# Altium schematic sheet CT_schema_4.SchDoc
size 367 x 243 mm
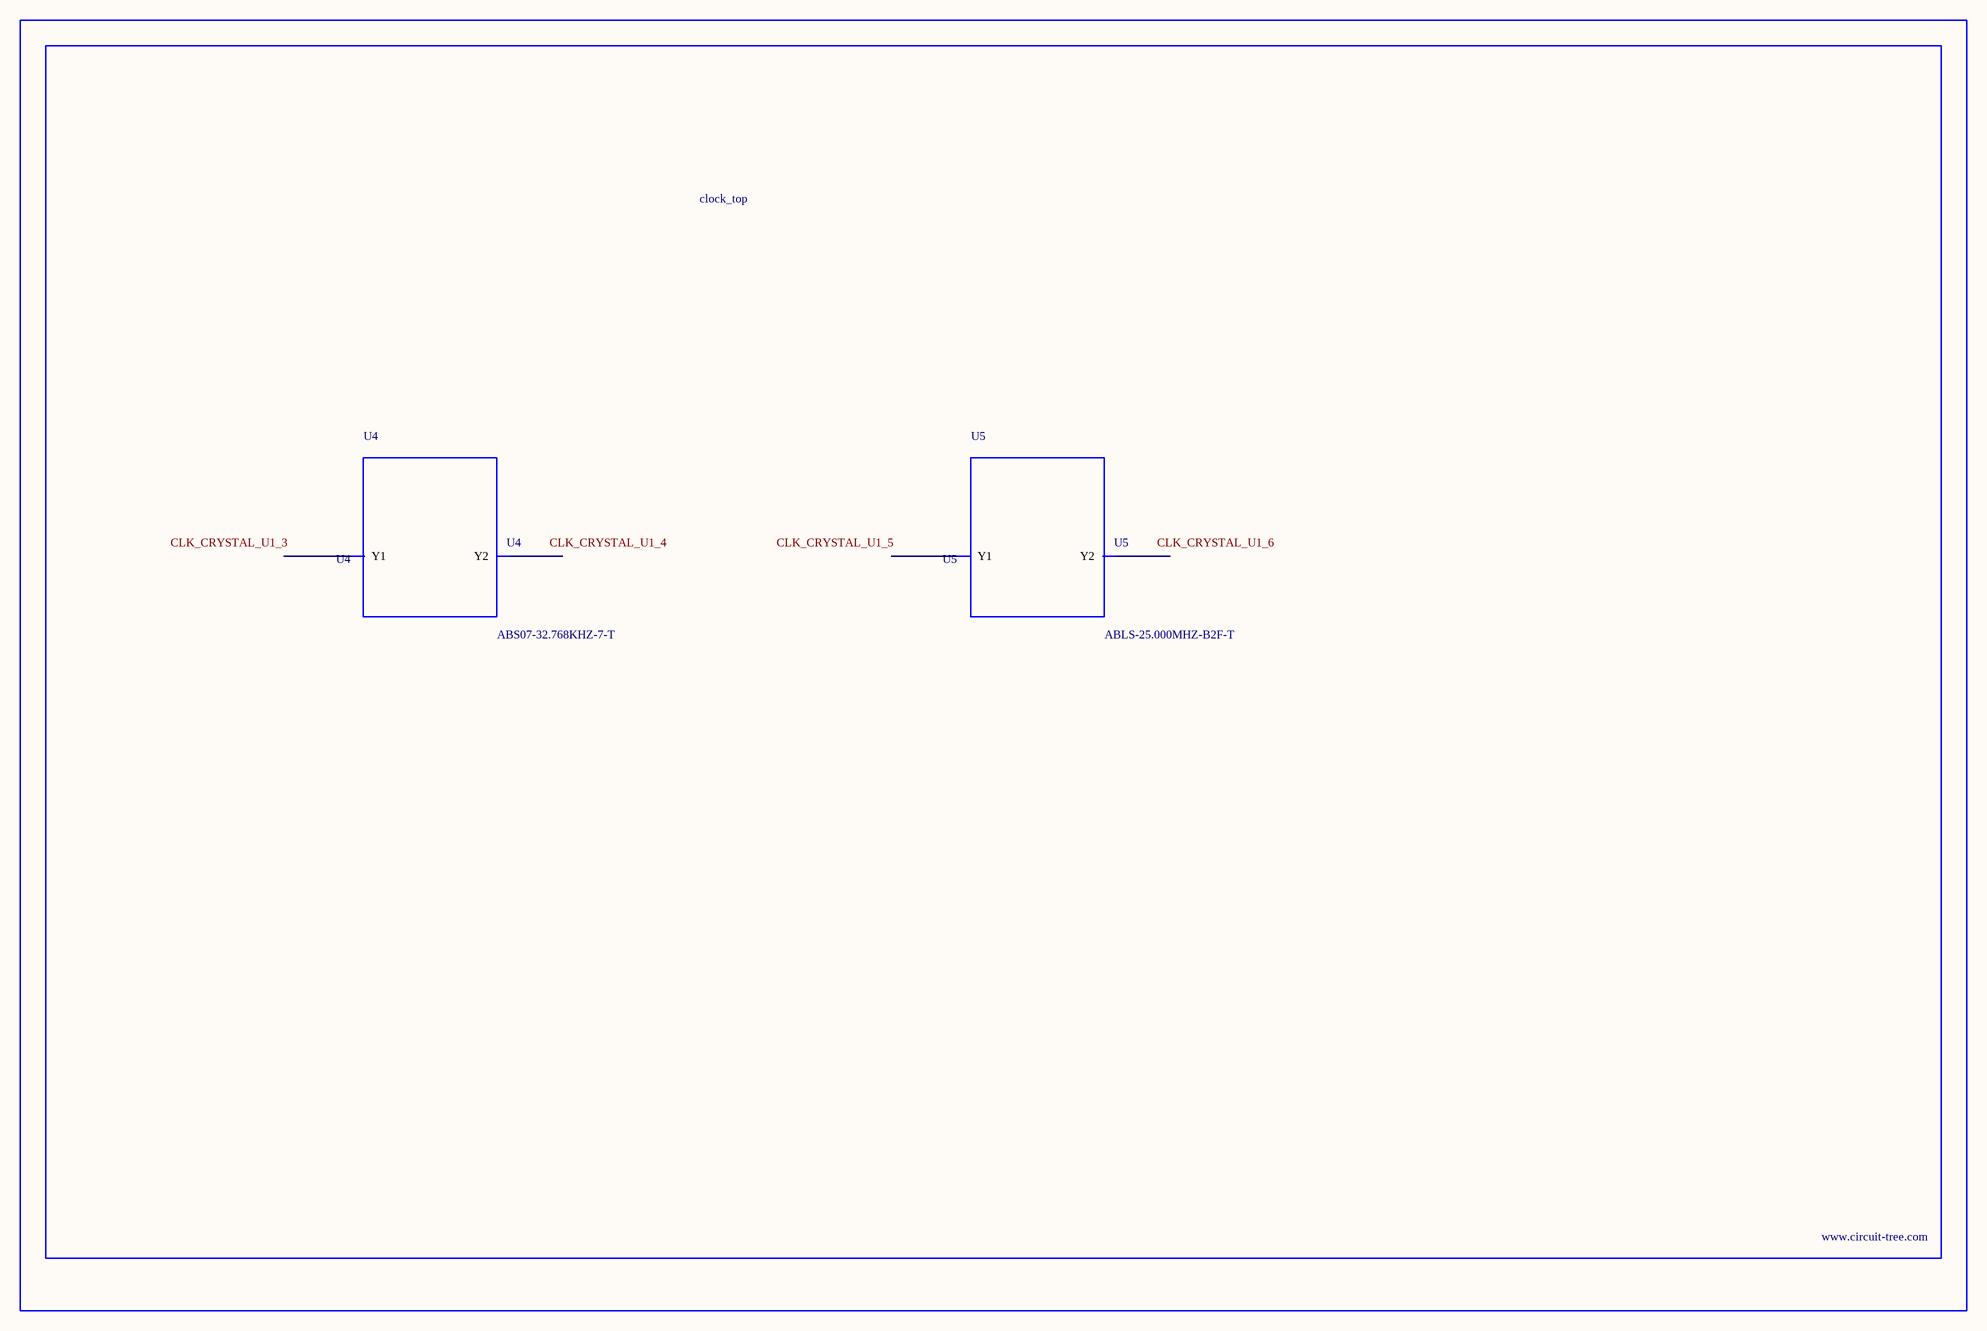
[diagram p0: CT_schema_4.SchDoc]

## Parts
BORDER3  (no value)
U4  ABS07-32.768KHZ-7-T  [ABS07-32.768KHZ-7-T]
U5  ABLS-25.000MHZ-B2F-T  [ABLS-25.000MHZ-B2F-T]

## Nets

Not connected (* = marked no-connect by the designer): U4 1(Y1) 2(Y2); U5 1(Y1) 2(Y2)

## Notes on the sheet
- Labels drawn without touching a wire or pin: CLK_CRYSTAL_U1_3, CLK_CRYSTAL_U1_4, CLK_CRYSTAL_U1_5, CLK_CRYSTAL_U1_6

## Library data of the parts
BORDER3 = BORDER_PAGE3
